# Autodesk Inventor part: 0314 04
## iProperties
Created: 2016-04
Part Number: 0314 04
Checked By: TraceParts S.A.
Catalog Web Link: www.traceparts.com
Description: Chassis plug acc. to IEC 61076-2-106, IP 68, with threaded joint and solder terminals, for front mounting - 0314 04
Vendor: LUMBERG
Document SubType Name: Modeling
Designer: TraceParts
Company: TraceParts S.A.
Title: Chassis plug acc. to IEC 61076-2-106, IP 68, with threaded joint and solder terminals, for front mounting - 0314 04
Author: TraceParts
REFERENCE: 0314 04
poles: 4
SUPPLIER: LUMBERG
DESIGN: Chassis plug acc. to IEC 61076-2-106, IP 68, with threaded joint and solder terminals, for front mounting - 0314 04
ue: 50
TraceParts.PartStatus: Published
TraceParts.PartNumber: 10-10112014-103001
TraceParts.PartLanguage: en
TraceParts.InstanceId: 10-10112014-103001DOK71L3HOKZ357W9I71LO58LJ
TraceParts.PartTitle: 0314
TraceParts.PartVersion: 1.0.7
TRACEPARTS: TRACEPARTS
TraceParts.ClassPath: LUMBERG:/F_LUMBERG/LUMBERG.020/10-10112014-103001
